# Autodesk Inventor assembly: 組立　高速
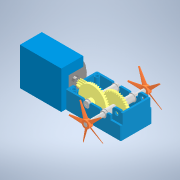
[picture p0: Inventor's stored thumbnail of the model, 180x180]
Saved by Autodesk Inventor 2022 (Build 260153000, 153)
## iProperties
Created: 2024-12
Part Number: 組立　高速
Document SubType Name: Assembly
Designer: jsat7
Author: jsat7
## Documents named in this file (17)
- C:\Users\shimizu\Desktop\自在ギヤボックス\組立図\組立　高速.iam
- C:\Users\shimizu\Desktop\自在ギヤボックス\部品図\ボックス　下.ipt
- C:\Users\shimizu\Desktop\自在ギヤボックス\部品図\B3.ipt
- C:\Users\shimizu\Desktop\自在ギヤボックス\部品図\B4.ipt
- C:\Users\shimizu\Desktop\自在ギヤボックス\部品図\B6.ipt
- C:\Users\shimizu\Desktop\自在ギヤボックス\部品図\丸棒.ipt
- C:\Users\shimizu\Desktop\自在ギヤボックス\部品図\クラウンギア.iam
- C:\Users\shimizu\Desktop\自在ギヤボックス\部品図\モーター　ピニオンギア.iam
- C:\Users\shimizu\Desktop\自在ギヤボックス\部品図\モーター　箱.ipt
- C:\Users\shimizu\Desktop\自在ギヤボックス\部品図\ピニオンギア.ipt
- C:\Users\shimizu\Desktop\自在ギヤボックス\部品図\六角シャフト.ipt
- C:\Users\shimizu\Desktop\自在ギヤボックス\部品図\B7.ipt
- C:\Users\shimizu\Desktop\自在ギヤボックス\部品図\特殊平ギア.ipt
- C:\Users\shimizu\Desktop\自在ギヤボックス\部品図\固定器具.ipt
- C:\Users\shimizu\Desktop\自在ギヤボックス\部品図\B1.ipt
- C:\Users\shimizu\Desktop\自在ギヤボックス\部品図\B2.ipt
- C:\Users\shimizu\Desktop\自在ギヤボックス\部品図\プロペラ.ipt
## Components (15 placed, 13 different names)
1. B4:1 — メイト:2, フラッシュ:2, メイト:3
2. B6:1 — メイト:1, メイト:28, メイト:29, フラッシュ:13
3. 丸棒:1 — メイト:3, メイト:5, メイト:28, メイト:33
4. クラウンギア:1 [sub-assembly] — メイト:5, 回転:1, メイト:29, メイト:32, 回転:2
5. モーター　ピニオンギア:1 [sub-assembly] — フラッシュ:5, フラッシュ:6, メイト:13, メイト:14, フラッシュ:8
6. 平歯車1:1 — メイト:14, フラッシュ:8, 回転:1, 角度:1
7. 六角シャフト:1 — メイト:26, リジッド:1, リジッド:2, メイト:35, リジッド:3, リジッド:4
8. B3:1 — メイト:24, フラッシュ:11, メイト:30
9. B7:1 — メイト:25, フラッシュ:12, メイト:26
10. 平歯車1:2 — メイト:30, リジッド:1, メイト:31, 回転:2
11. 固定器具:1 — メイト:31, リジッド:2, メイト:34
12. B1:1 — メイト:32, メイト:33
13. B2:1 — メイト:34, メイト:35
14. プロペラ:1 — リジッド:3
15. プロペラ:2 — リジッド:4
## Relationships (31: Mate 17, Flush 7, WeldJoint 4, RelateRotation 2, Angle 1)
- メイト:1 [Mate]: B6:1
- メイト:2 [Mate]: B4:1
- フラッシュ:2 [Flush]: B4:1
- メイト:3 [Mate]: B4:1 ↔ 丸棒:1
- メイト:5 [Mate]: 丸棒:1 ↔ クラウンギア:1
- フラッシュ:5 [Flush]: モーター　ピニオンギア:1
- フラッシュ:6 [Flush]: モーター　ピニオンギア:1
- メイト:13 [Mate]: モーター　ピニオンギア:1
- メイト:14 [Mate]: モーター　ピニオンギア:1 ↔ 平歯車1:1
- フラッシュ:8 [Flush]: モーター　ピニオンギア:1 ↔ 平歯車1:1
- 回転:1 [RelateRotation]: クラウンギア:1 ↔ 平歯車1:1
- 角度:1 [Angle]: 平歯車1:1
- メイト:24 [Mate]: B3:1
- フラッシュ:11 [Flush]: B3:1
- メイト:25 [Mate]: B7:1
- フラッシュ:12 [Flush]: B7:1
- メイト:26 [Mate]: 六角シャフト:1 ↔ B7:1
- メイト:28 [Mate]: B6:1 ↔ 丸棒:1
- メイト:29 [Mate]: B6:1 ↔ クラウンギア:1
- フラッシュ:13 [Flush]: B6:1
- メイト:30 [Mate]: B3:1 ↔ 平歯車1:2
- リジッド:1 [WeldJoint]: 六角シャフト:1 ↔ 平歯車1:2
- メイト:31 [Mate]: 平歯車1:2 ↔ 固定器具:1
- リジッド:2 [WeldJoint]: 六角シャフト:1 ↔ 固定器具:1
- メイト:32 [Mate]: クラウンギア:1 ↔ B1:1
- メイト:33 [Mate]: 丸棒:1 ↔ B1:1
- メイト:34 [Mate]: 固定器具:1 ↔ B2:1
- メイト:35 [Mate]: 六角シャフト:1 ↔ B2:1
- 回転:2 [RelateRotation]: クラウンギア:1 ↔ 平歯車1:2
- リジッド:3 [WeldJoint]: 六角シャフト:1 ↔ プロペラ:1
- リジッド:4 [WeldJoint]: 六角シャフト:1 ↔ プロペラ:2
